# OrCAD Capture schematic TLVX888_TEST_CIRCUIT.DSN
size A; title: TLVx888 Low Noise, Zero-Drift, Wide-Bandwidth, Mux-Friendly; rev: 1.0; note: Datasheet: SBOSAG5 - DEC "24  EVM: N/A
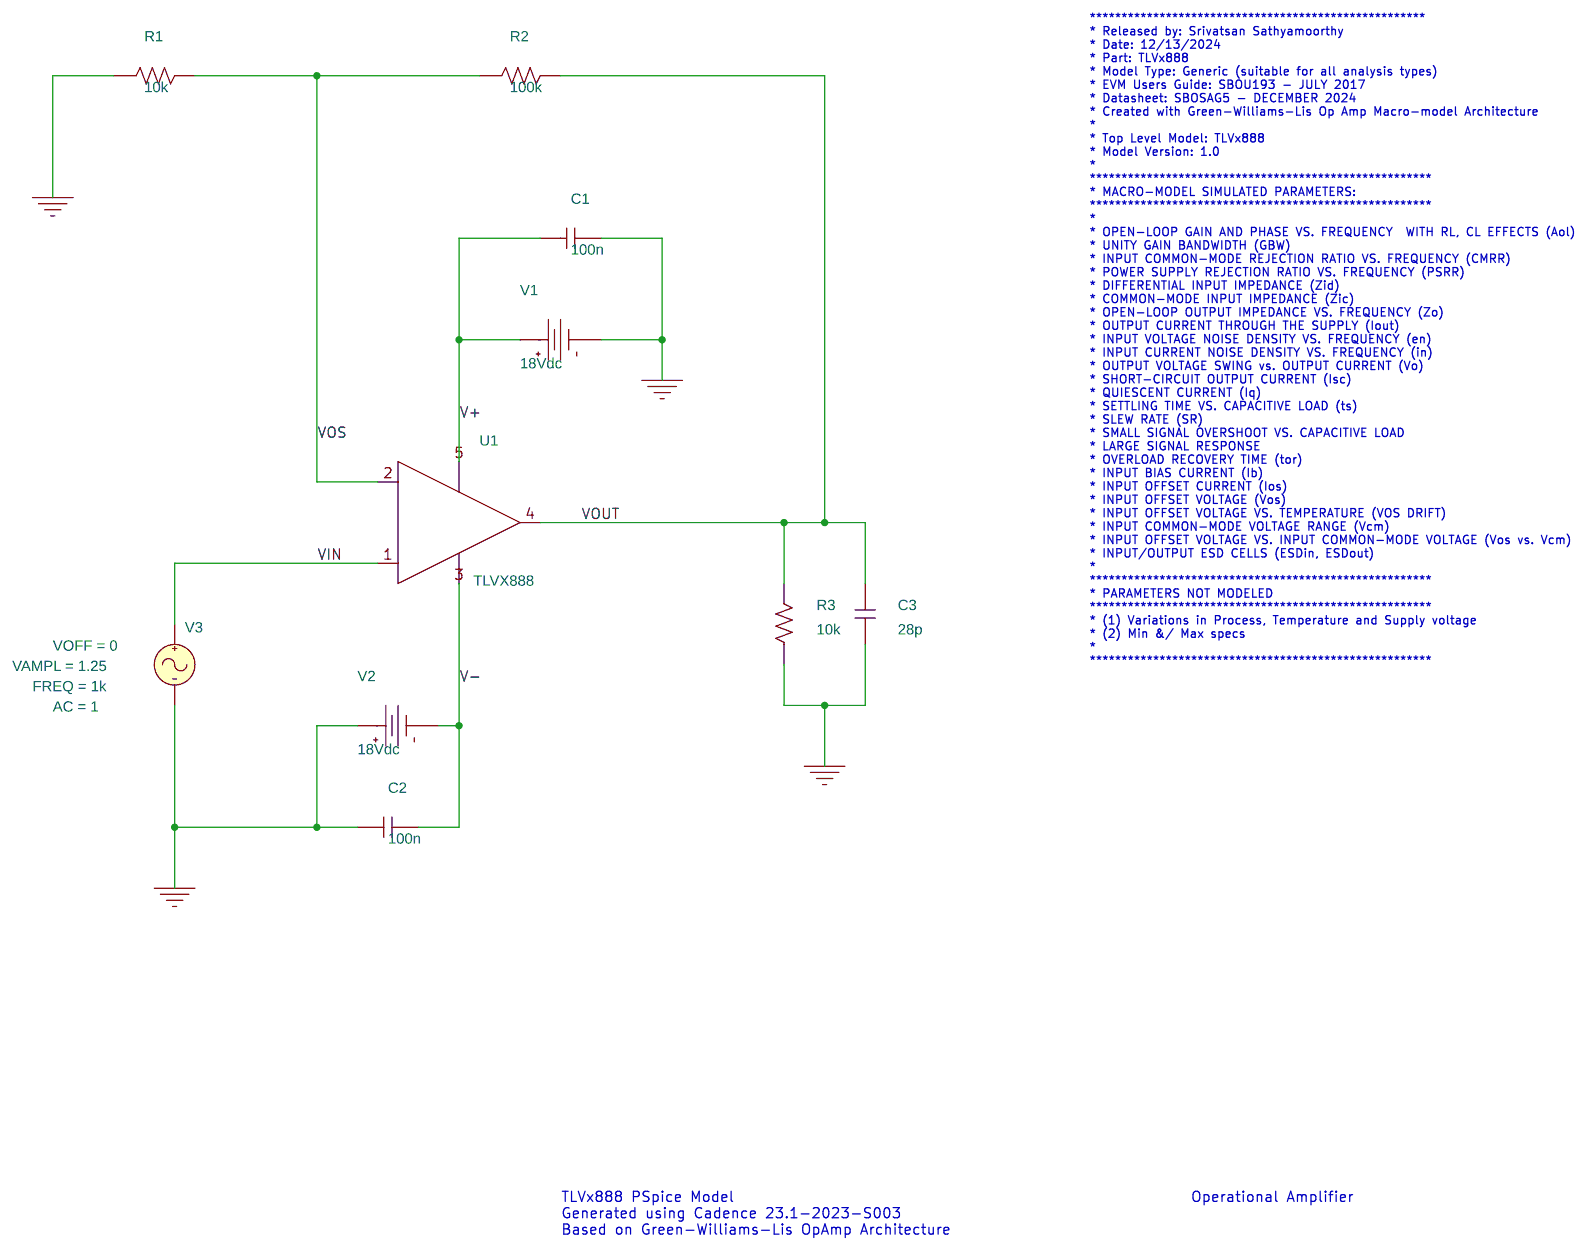
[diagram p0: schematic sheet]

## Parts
C1  100n  [cap196]
C2  100n  [cap196]
C3  28p  [cap196]
R1  10k  [AXRC05]
R2  100k  [AXRC05]
R3  10k  [AXRC05]
U1  TLVX888
V1  VDC
V2  VDC
V3  VSIN

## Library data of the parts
C1-C3 = C
R1-R3 = R
U1 = TLVX888
V1 V2 = VDC: DC: 18Vdc
V3 = VSIN: AC: 1; FREQ: 1k; VAMPL: 1.25; VOFF: 0

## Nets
VIN: U1.1(+) V3.1(+)
0: C1.2 C2.1 C3.1 R1.1 R3.1 V1.1(-) V2.0(+) V3.2(-)
V+: C1.1 U1.5(V+) V1.0(+)
V-: C2.2 U1.3(V-) V2.1(-)
VOS: R1.2 R2.1 U1.2(-)
VOUT: C3.2 R2.2 R3.2 U1.4(OUT)

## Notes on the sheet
- *****************************************************
  * Released by: Srivatsan Sathyamoorthy
  * Date: 12/13/2024
  * Part: TLVx888
  * Model Type: Generic (suitable for all analysis types)
  * EVM Users Guide: SBOU193 - JULY 2017
  * Datasheet: SBOSAG5 - DECEMBER 2024
  * Created with Green-Williams-Lis Op Amp Macro-model Architecture
  *
  * Top Level Model: TLVx888
  * Model Version: 1.0
  *
  ******************************************************
  * MACRO-MODEL SIMULATED PARAMETERS:
  ******************************************************
  *
  * OPEN-LOOP GAIN AND PHASE VS. FREQUENCY  WITH RL, CL EFFECTS (Aol)
  * UNITY GAIN BANDWIDTH (GBW)
  * INPUT COMMON-MODE REJECTION RATIO VS. FREQUENCY (CMRR)
  * POWER SUPPLY REJECTION RATIO VS. FREQUENCY (PSRR)
  * DIFFERENTIAL INPUT IMPEDANCE (Zid)
  * COMMON-MODE INPUT IMPEDANCE (Zic)
  * OPEN-LOOP OUTPUT IMPEDANCE VS. FREQUENCY (Zo)
  * OUTPUT CURRENT THROUGH THE SUPPLY (Iout)
  * INPUT VOLTAGE NOISE DENSITY VS. FREQUENCY (en)
  * INPUT CURRENT NOISE DENSITY VS. FREQUENCY (in)
  * OUTPUT VOLTAGE SWING vs. OUTPUT CURRENT (Vo)
  * SHORT-CIRCUIT OUTPUT CURRENT (Isc)
  * QUIESCENT CURRENT (Iq)
  * SETTLING TIME VS. CAPACITIVE LOAD (ts)
  * SLEW RATE (SR)
  * SMALL SIGNAL OVERSHOOT VS. CAPACITIVE LOAD
  * LARGE SIGNAL RESPONSE
  * OVERLOAD RECOVERY TIME (tor)
  * INPUT BIAS CURRENT (Ib)
  * INPUT OFFSET CURRENT (Ios)
  * INPUT OFFSET VOLTAGE (Vos)
  * INPUT OFFSET VOLTAGE VS. TEMPERATURE (VOS DRIFT)
  * INPUT COMMON-MODE VOLTAGE RANGE (Vcm)
  * INPUT OFFSET VOLTAGE VS. INPUT COMMON-MODE VOLTAGE (Vos vs. Vcm)
  * INPUT/OUTPUT ESD CELLS (ESDin, ESDout)
  *
  ******************************************************
  * PARAMETERS NOT MODELED
  ******************************************************
  * (1) Variations in Process, Temperature and Supply voltage
  * (2) Min &/ Max specs
  *
  ******************************************************
- TLVx888 PSpice Model
  Generated using Cadence 23.1-2023-S003
  Based on Green-Williams-Lis OpAmp Architecture
- Operational Amplifier
